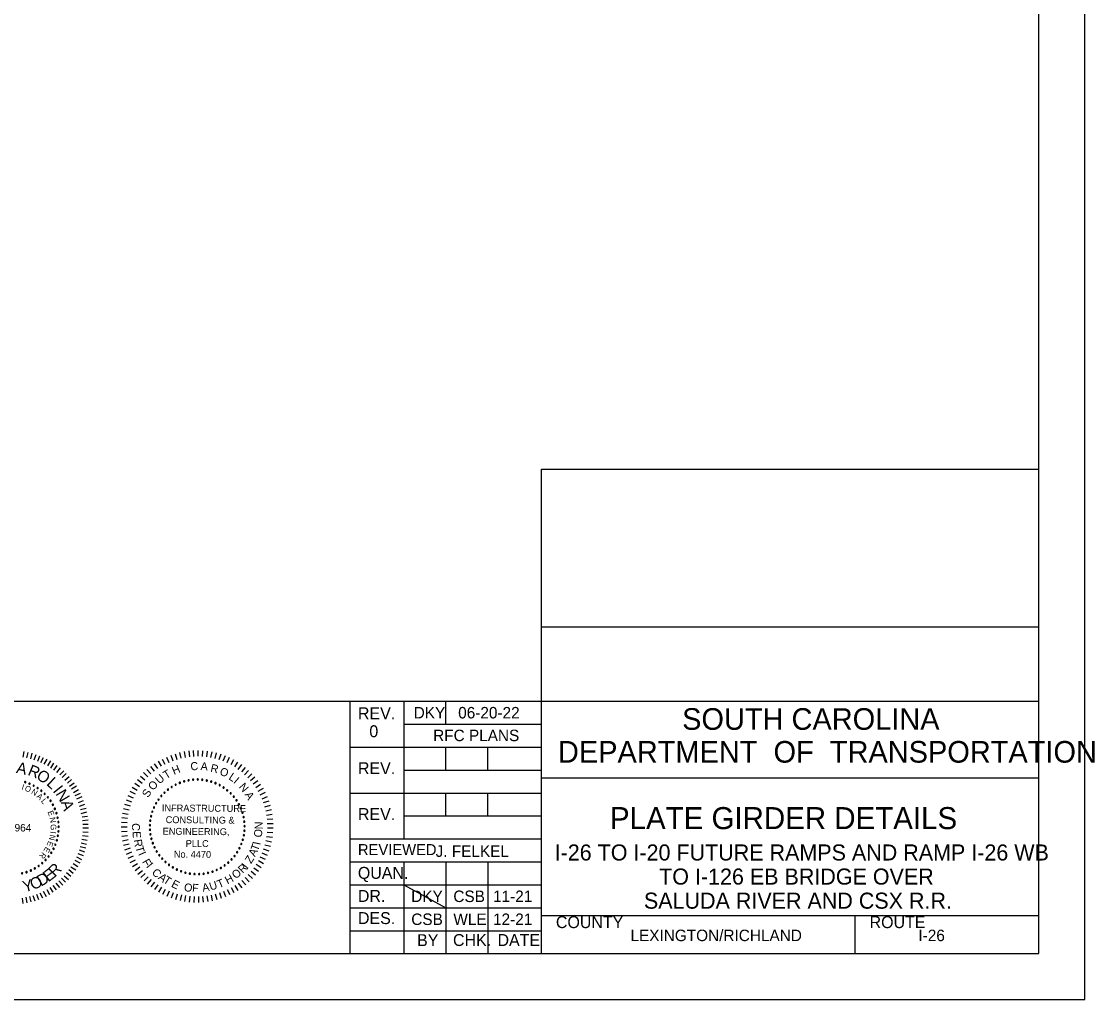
# Model space of a CAD drawing. Extents: x -305 to -161, y -187 to -99.
# Drawn here: x -207.5 to -160.75, y -187.49 to -144.87 of the extents above; entities that cross this region are included whole.
import ezdxf

# ---------------------------------------------------------------- set-up
doc = ezdxf.new("R2010")
doc.units = 0
for name, color, linetype in [('BR_BORDER LINES', 7, 'Continuous'), ('BR_TEXT', 7, 'Continuous'), ('Level 31', 7, 'Continuous')]:
    doc.layers.add(name, color=color, linetype=linetype)

msp = doc.modelspace()

# ---------------------------------------------------------------- linework, layer by layer
at = {"layer": 'BR_BORDER LINES'}
for p, q in [((-163.178, -185.489), (-163.178, -101.489)), ((-184.846, -185.489), (-184.846, -164.383)), ((-184.846, -164.383), (-163.178, -164.383)), ((-184.845, -171.242), (-163.178, -171.242)), ((-214.64, -174.489), (-193.18, -174.489)), ((-193.18, -185.489), (-193.18, -174.489)), ((-193.18, -174.489), (-163.178, -174.489)), ((-190.846, -174.489), (-190.846, -180.489)), ((-189.013, -175.489), (-189.013, -174.489)), ((-190.846, -175.489), (-184.846, -175.489)), ((-193.18, -176.489), (-184.846, -176.489)), ((-189.013, -177.489), (-189.013, -176.489)), ((-187.179, -177.489), (-187.179, -176.489)), ((-190.846, -177.489), (-184.846, -177.489)), ((-184.846, -177.822), (-184.846, -177.822)), ((-184.846, -177.823), (-163.178, -177.823)), ((-193.18, -178.489), (-184.846, -178.489)), ((-189.013, -179.489), (-189.013, -178.489)), ((-187.179, -179.489), (-187.179, -178.489)), ((-190.846, -179.489), (-184.846, -179.489)), ((-193.18, -180.489), (-184.846, -180.489)), ((-193.18, -181.489), (-184.846, -181.489)), ((-190.846, -181.489), (-190.846, -185.489)), ((-189.013, -181.489), (-189.013, -185.489)), ((-187.179, -181.489), (-187.179, -185.489)), ((-193.18, -182.489), (-184.846, -182.489)), ((-193.18, -183.489), (-184.846, -183.489)), ((-184.846, -183.823), (-163.178, -183.823)), ((-184.456, -183.823), (-163.178, -183.823)), ((-171.179, -185.489), (-171.179, -183.823)), ((-193.18, -184.489), (-184.846, -184.489)), ((-297.843, -185.489), (-163.178, -185.489))]:
    msp.add_line(p, q, dxfattribs=at)
at = {"layer": 'BR_TEXT'}
for p, q in [((-207.426, -176.925), (-207.382, -176.681)), ((-207.264, -176.957), (-207.208, -176.721)), ((-200.417, -176.685), (-200.373, -176.936)), ((-200.217, -176.656), (-200.188, -176.909)), ((-200.016, -176.64), (-200.002, -176.894)), ((-199.814, -176.636), (-199.816, -176.89)), ((-199.612, -176.644), (-199.63, -176.898)), ((-199.411, -176.664), (-199.444, -176.917)), ((-199.212, -176.697), (-199.26, -176.947)), ((-207.1, -176.999), (-207.036, -176.756)), ((-206.953, -177.042), (-206.865, -176.813)), ((-206.795, -177.095), (-206.708, -176.862)), ((-206.652, -177.165), (-206.54, -176.942)), ((-206.508, -177.234), (-206.383, -177.012)), ((-206.358, -177.308), (-206.229, -177.093)), ((-206.225, -177.405), (-206.089, -177.19)), ((-201.546, -177.106), (-201.415, -177.324)), ((-201.37, -177.007), (-201.252, -177.233)), ((-201.188, -176.92), (-201.084, -177.153)), ((-201.001, -176.844), (-200.912, -177.082)), ((-200.81, -176.779), (-200.735, -177.023)), ((-200.615, -176.726), (-200.555, -176.974)), ((-199.015, -176.741), (-199.079, -176.988)), ((-198.821, -176.798), (-198.9, -177.04)), ((-198.631, -176.866), (-198.724, -177.103)), ((-198.446, -176.946), (-198.553, -177.177)), ((-198.265, -177.037), (-198.387, -177.261)), ((-198.091, -177.139), (-198.226, -177.355)), ((-206.091, -177.492), (-205.946, -177.291)), ((-205.962, -177.596), (-205.799, -177.398)), ((-205.836, -177.696), (-205.663, -177.519)), ((-205.723, -177.807), (-205.55, -177.634)), ((-202.182, -177.601), (-202.002, -177.781)), ((-202.035, -177.463), (-201.866, -177.654)), ((-201.879, -177.334), (-201.723, -177.535)), ((-201.716, -177.215), (-201.572, -177.425)), ((-197.923, -177.251), (-198.071, -177.458)), ((-197.762, -177.373), (-197.922, -177.571)), ((-197.609, -177.505), (-197.781, -177.693)), ((-197.464, -177.646), (-197.647, -177.823)), ((-205.611, -177.932), (-205.421, -177.765)), ((-205.502, -178.06), (-205.316, -177.907)), ((-205.407, -178.194), (-205.21, -178.038)), ((-202.57, -178.065), (-202.36, -178.21)), ((-202.45, -177.903), (-202.25, -178.06)), ((-202.321, -177.748), (-202.13, -177.917)), ((-197.329, -177.795), (-197.522, -177.961)), ((-197.202, -177.952), (-197.405, -178.106)), ((-197.086, -178.117), (-197.298, -178.258)), ((-205.319, -178.312), (-205.109, -178.183)), ((-205.231, -178.46), (-205.017, -178.335)), ((-205.16, -178.598), (-204.929, -178.49)), ((-202.867, -178.593), (-202.634, -178.696)), ((-202.779, -178.411), (-202.553, -178.529)), ((-202.679, -178.235), (-202.461, -178.366)), ((-196.979, -178.289), (-197.199, -178.417)), ((-196.883, -178.467), (-197.111, -178.581)), ((-205.089, -178.746), (-204.862, -178.648)), ((-205.022, -178.901), (-204.795, -178.817)), ((-204.968, -179.063), (-204.738, -178.976)), ((-203.009, -178.97), (-202.766, -179.045)), ((-202.944, -178.779), (-202.705, -178.869)), ((-196.799, -178.65), (-197.033, -178.75)), ((-196.725, -178.838), (-196.965, -178.924)), ((-196.664, -179.03), (-196.908, -179.101)), ((-204.928, -179.207), (-204.688, -179.151)), ((-204.895, -179.376), (-204.654, -179.316)), ((-204.862, -179.52), (-204.625, -179.491)), ((-203.104, -179.363), (-202.853, -179.407)), ((-203.063, -179.165), (-202.815, -179.225)), ((-196.614, -179.226), (-196.862, -179.282)), ((-196.576, -179.424), (-196.827, -179.465)), ((-204.836, -179.685), (-204.592, -179.66)), ((-204.831, -179.843), (-204.59, -179.845)), ((-203.156, -179.965), (-202.901, -179.964)), ((-203.151, -179.764), (-202.897, -179.777)), ((-203.134, -179.562), (-202.881, -179.592)), ((-196.55, -179.625), (-196.804, -179.65)), ((-196.537, -179.826), (-196.791, -179.836)), ((-204.841, -180.334), (-204.598, -180.367)), ((-204.833, -180.18), (-204.593, -180.189)), ((-204.822, -180.008), (-204.578, -180.01)), ((-203.149, -180.167), (-202.895, -180.15)), ((-203.129, -180.368), (-202.877, -180.335)), ((-196.57, -180.43), (-196.822, -180.393)), ((-196.547, -180.23), (-196.8, -180.208)), ((-196.535, -180.028), (-196.79, -180.022)), ((-204.942, -180.824), (-204.702, -180.885)), ((-204.906, -180.656), (-204.666, -180.713)), ((-204.87, -180.499), (-204.634, -180.538)), ((-203.097, -180.568), (-202.847, -180.52)), ((-203.053, -180.765), (-202.807, -180.701)), ((-202.997, -180.959), (-202.755, -180.881)), ((-196.653, -180.825), (-196.899, -180.758)), ((-196.606, -180.629), (-196.855, -180.577)), ((-205.11, -181.272), (-204.884, -181.384)), ((-205.04, -181.125), (-204.814, -181.213)), ((-204.984, -180.971), (-204.755, -181.059)), ((-202.93, -181.149), (-202.693, -181.056)), ((-202.851, -181.335), (-202.62, -181.228)), ((-202.761, -181.516), (-202.536, -181.395)), ((-196.867, -181.392), (-197.096, -181.281)), ((-196.784, -181.207), (-197.02, -181.111)), ((-196.713, -181.018), (-196.954, -180.936)), ((-205.437, -181.826), (-205.243, -181.975)), ((-205.347, -181.71), (-205.139, -181.839)), ((-205.257, -181.563), (-205.045, -181.692)), ((-205.183, -181.416), (-204.954, -181.538)), ((-202.66, -181.69), (-202.443, -181.556)), ((-202.548, -181.859), (-202.34, -181.711)), ((-202.426, -182.02), (-202.228, -181.86)), ((-197.179, -181.91), (-197.385, -181.759)), ((-197.065, -181.743), (-197.279, -181.605)), ((-196.96, -181.57), (-197.182, -181.446)), ((-205.874, -182.313), (-205.704, -182.5)), ((-205.76, -182.194), (-205.589, -182.377)), ((-205.645, -182.092), (-205.458, -182.258)), ((-205.535, -181.959), (-205.351, -182.118)), ((-202.295, -182.173), (-202.107, -182.002)), ((-202.155, -182.319), (-201.977, -182.136)), ((-202.006, -182.455), (-201.84, -182.262)), ((-197.733, -182.495), (-197.895, -182.3)), ((-197.581, -182.362), (-197.756, -182.176)), ((-197.438, -182.219), (-197.623, -182.045)), ((-197.304, -182.068), (-197.5, -181.905)), ((-206.554, -182.768), (-206.432, -182.992)), ((-206.402, -182.69), (-206.277, -182.907)), ((-206.268, -182.602), (-206.135, -182.812)), ((-206.133, -182.517), (-205.99, -182.71)), ((-206.002, -182.415), (-205.842, -182.605)), ((-201.849, -182.582), (-201.695, -182.379)), ((-201.685, -182.699), (-201.543, -182.487)), ((-201.513, -182.806), (-201.385, -182.586)), ((-201.336, -182.903), (-201.221, -182.675)), ((-201.153, -182.988), (-201.053, -182.754)), ((-198.596, -183.012), (-198.692, -182.777)), ((-198.411, -182.93), (-198.522, -182.701)), ((-198.232, -182.837), (-198.356, -182.615)), ((-198.059, -182.734), (-198.196, -182.519)), ((-197.892, -182.62), (-198.042, -182.414)), ((-207.476, -183.065), (-207.437, -183.299)), ((-207.315, -183.022), (-207.262, -183.27)), ((-207.15, -182.996), (-207.09, -183.233)), ((-207.002, -182.949), (-206.918, -183.183)), ((-206.843, -182.902), (-206.759, -183.13)), ((-206.699, -182.835), (-206.591, -183.059)), ((-200.965, -183.062), (-200.879, -182.822)), ((-200.773, -183.125), (-200.702, -182.88)), ((-200.577, -183.175), (-200.521, -182.927)), ((-200.379, -183.214), (-200.338, -182.962)), ((-200.179, -183.24), (-200.154, -182.987)), ((-199.978, -183.254), (-199.968, -183)), ((-199.776, -183.256), (-199.781, -183.002)), ((-199.574, -183.246), (-199.595, -182.992)), ((-199.373, -183.223), (-199.41, -182.971)), ((-199.174, -183.188), (-199.226, -182.939)), ((-198.978, -183.142), (-199.045, -182.896)), ((-198.785, -183.083), (-198.867, -182.842))]:
    msp.add_line(p, q, dxfattribs=at)
for centre, start, end in [((-207.337, -178.015), 162.9114, 342.9114), ((-207.337, -178.015), 342.9114, 162.9114), ((-207.15, -178.083), 157.373, 337.373), ((-207.15, -178.083), 337.373, 157.373), ((-200.785, -178.127), 27.2191, 207.2191), ((-200.785, -178.127), 207.2191, 27.2191), ((-200.603, -178.045), 21.6807, 201.6807), ((-200.603, -178.045), 201.6807, 21.6807), ((-200.414, -177.98), 16.1422, 196.1422), ((-200.414, -177.98), 196.1422, 16.1422), ((-200.22, -177.935), 10.6038, 190.6038), ((-200.22, -177.935), 190.6038, 10.6038), ((-200.023, -177.908), 5.0653, 185.0653), ((-200.023, -177.908), 185.0653, 5.0653), ((-199.824, -177.9), 359.5268, 179.5268), ((-199.824, -177.9), 179.5268, 359.5268), ((-199.625, -177.912), 353.9884, 173.9884), ((-199.625, -177.912), 173.9884, 353.9884), ((-199.428, -177.943), 168.4499, 348.4499), ((-199.428, -177.943), 348.4499, 168.4499), ((-199.235, -177.992), 162.9114, 342.9114), ((-199.235, -177.992), 342.9114, 162.9114), ((-199.047, -178.06), 157.373, 337.373), ((-199.047, -178.06), 337.373, 157.373), ((-198.867, -178.146), 331.8345, 151.8345), ((-206.97, -178.169), 151.8345, 331.8345), ((-206.97, -178.169), 331.8345, 151.8345), ((-206.8, -178.272), 146.2961, 326.2961), ((-206.8, -178.272), 326.2961, 146.2961), ((-206.639, -178.39), 140.7576, 320.7576), ((-206.639, -178.39), 320.7576, 140.7576), ((-206.492, -178.524), 135.2191, 315.2191), ((-206.492, -178.524), 315.2191, 135.2191), ((-201.408, -178.617), 49.373, 229.373), ((-201.27, -178.472), 43.8345, 223.8345), ((-201.27, -178.472), 223.8345, 43.8345), ((-201.12, -178.341), 38.2961, 218.2961), ((-201.12, -178.341), 218.2961, 38.2961), ((-200.957, -178.226), 32.7576, 212.7576), ((-200.957, -178.226), 212.7576, 32.7576), ((-198.867, -178.146), 151.8345, 331.8345), ((-198.697, -178.249), 146.2961, 326.2961), ((-198.697, -178.249), 326.2961, 146.2961), ((-198.537, -178.368), 140.7576, 320.7576), ((-198.537, -178.368), 320.7576, 140.7576), ((-198.389, -178.502), 135.2191, 315.2191), ((-198.389, -178.502), 315.2191, 135.2191), ((-206.357, -178.671), 129.6807, 309.6807), ((-206.357, -178.671), 309.6807, 129.6807), ((-206.238, -178.831), 124.1422, 304.1422), ((-206.238, -178.831), 304.1422, 124.1422), ((-206.135, -179.001), 118.6038, 298.6038), ((-206.135, -179.001), 298.6038, 118.6038), ((-201.637, -178.942), 60.4499, 240.4499), ((-201.637, -178.942), 240.4499, 60.4499), ((-201.53, -178.774), 54.9114, 234.9114), ((-201.53, -178.774), 234.9114, 54.9114), ((-201.408, -178.617), 229.373, 49.373), ((-198.255, -178.649), 129.6807, 309.6807), ((-198.255, -178.649), 309.6807, 129.6807), ((-198.135, -178.809), 124.1422, 304.1422), ((-198.135, -178.809), 304.1422, 124.1422), ((-198.032, -178.979), 118.6038, 298.6038), ((-198.032, -178.979), 298.6038, 118.6038), ((-206.048, -179.181), 113.0653, 293.0653), ((-206.048, -179.181), 293.0653, 113.0653), ((-205.979, -179.368), 107.5268, 287.5268), ((-205.979, -179.368), 287.5268, 107.5268), ((-201.854, -179.497), 77.0653, 257.0653), ((-201.854, -179.497), 257.0653, 77.0653), ((-201.8, -179.305), 71.5268, 251.5268), ((-201.8, -179.305), 251.5268, 71.5268), ((-201.727, -179.12), 65.9884, 245.9884), ((-201.727, -179.12), 245.9884, 65.9884), ((-197.945, -179.159), 113.0653, 293.0653), ((-197.945, -179.159), 293.0653, 113.0653), ((-197.876, -179.346), 107.5268, 287.5268), ((-197.876, -179.346), 287.5268, 107.5268), ((-197.826, -179.538), 101.9884, 281.9884), ((-197.826, -179.538), 281.9884, 101.9884), ((-205.929, -179.561), 101.9884, 281.9884), ((-205.929, -179.561), 281.9884, 101.9884), ((-205.897, -179.758), 96.4499, 276.4499), ((-205.885, -179.957), 90.9114, 270.9114), ((-205.897, -179.758), 276.4499, 96.4499), ((-205.885, -179.957), 270.9114, 90.9114), ((-201.906, -179.892), 88.1422, 268.1422), ((-201.89, -179.693), 82.6038, 262.6038), ((-201.906, -179.892), 268.1422, 88.1422), ((-201.89, -179.693), 262.6038, 82.6038), ((-197.795, -179.735), 96.4499, 276.4499), ((-197.782, -179.934), 90.9114, 270.9114), ((-197.795, -179.735), 276.4499, 96.4499), ((-197.782, -179.934), 270.9114, 90.9114), ((-205.918, -180.353), 79.8345, 259.8345), ((-205.918, -180.353), 259.8345, 79.8345), ((-205.892, -180.156), 85.373, 265.373), ((-205.892, -180.156), 265.373, 85.373), ((-201.904, -180.091), 93.6807, 273.6807), ((-201.882, -180.289), 99.2191, 279.2191), ((-201.904, -180.091), 273.6807, 93.6807), ((-201.882, -180.289), 279.2191, 99.2191), ((-201.841, -180.484), 104.7576, 284.7576), ((-201.841, -180.484), 284.7576, 104.7576), ((-197.815, -180.331), 79.8345, 259.8345), ((-197.815, -180.331), 259.8345, 79.8345), ((-197.789, -180.133), 85.373, 265.373), ((-197.789, -180.133), 265.373, 85.373), ((-206.108, -180.918), 63.2191, 243.2191), ((-206.108, -180.918), 243.2191, 63.2191), ((-206.026, -180.737), 68.7576, 248.7576), ((-206.026, -180.737), 248.7576, 68.7576), ((-205.963, -180.548), 74.2961, 254.2961), ((-205.963, -180.548), 254.2961, 74.2961), ((-201.781, -180.675), 110.2961, 290.2961), ((-201.781, -180.675), 290.2961, 110.2961), ((-201.703, -180.858), 115.8345, 295.8345), ((-201.703, -180.858), 295.8345, 115.8345), ((-198.005, -180.896), 63.2191, 243.2191), ((-198.005, -180.896), 243.2191, 63.2191), ((-197.924, -180.714), 68.7576, 248.7576), ((-197.924, -180.714), 248.7576, 68.7576), ((-197.86, -180.525), 74.2961, 254.2961), ((-197.86, -180.525), 254.2961, 74.2961), ((-206.451, -181.406), 46.6038, 226.6038), ((-206.451, -181.406), 226.6038, 46.6038), ((-206.321, -181.255), 52.1422, 232.1422), ((-206.321, -181.255), 232.1422, 52.1422), ((-206.207, -181.092), 57.6807, 237.6807), ((-206.207, -181.092), 237.6807, 57.6807), ((-201.608, -181.033), 121.373, 301.373), ((-201.608, -181.033), 301.373, 121.373), ((-201.497, -181.199), 126.9114, 306.9114), ((-201.497, -181.199), 306.9114, 126.9114), ((-201.37, -181.352), 132.4499, 312.4499), ((-201.37, -181.352), 312.4499, 132.4499), ((-198.349, -181.383), 46.6038, 226.6038), ((-198.349, -181.383), 226.6038, 46.6038), ((-198.219, -181.232), 52.1422, 232.1422), ((-198.219, -181.232), 232.1422, 52.1422), ((-198.104, -181.069), 57.6807, 237.6807), ((-198.104, -181.069), 237.6807, 57.6807), ((-207.097, -181.865), 24.4499, 204.4499), ((-207.097, -181.865), 204.4499, 24.4499), ((-206.92, -181.774), 29.9884, 209.9884), ((-206.92, -181.774), 209.9884, 29.9884), ((-206.752, -181.667), 35.5268, 215.5268), ((-206.752, -181.667), 215.5268, 35.5268), ((-206.596, -181.543), 41.0653, 221.0653), ((-206.596, -181.543), 221.0653, 41.0653), ((-201.228, -181.493), 137.9884, 317.9884), ((-201.228, -181.493), 317.9884, 137.9884), ((-201.074, -181.619), 143.5268, 323.5268), ((-201.074, -181.619), 323.5268, 143.5268), ((-200.909, -181.73), 149.0653, 329.0653), ((-200.909, -181.73), 329.0653, 149.0653), ((-200.733, -181.825), 154.6038, 334.6038), ((-200.733, -181.825), 334.6038, 154.6038), ((-198.995, -181.842), 24.4499, 204.4499), ((-198.995, -181.842), 204.4499, 24.4499), ((-198.817, -181.752), 29.9884, 209.9884), ((-198.817, -181.752), 209.9884, 29.9884), ((-198.649, -181.644), 35.5268, 215.5268), ((-198.649, -181.644), 215.5268, 35.5268), ((-198.493, -181.521), 41.0653, 221.0653), ((-198.493, -181.521), 221.0653, 41.0653), ((-207.474, -181.993), 13.373, 193.373), ((-207.474, -181.993), 193.373, 13.373), ((-207.283, -181.938), 18.9114, 198.9114), ((-207.283, -181.938), 198.9114, 18.9114), ((-200.549, -181.902), 160.1422, 340.1422), ((-200.549, -181.902), 340.1422, 160.1422), ((-200.359, -181.961), 165.6807, 345.6807), ((-200.359, -181.961), 345.6807, 165.6807), ((-200.164, -182.001), 171.2191, 351.2191), ((-200.164, -182.001), 351.2191, 171.2191), ((-199.965, -182.022), 176.7576, 356.7576), ((-199.965, -182.022), 356.7576, 176.7576), ((-199.766, -182.024), 2.2961, 182.2961), ((-199.766, -182.024), 182.2961, 2.2961), ((-199.568, -182.007), 7.8345, 187.8345), ((-199.568, -182.007), 187.8345, 7.8345), ((-199.372, -181.971), 13.373, 193.373), ((-199.372, -181.971), 193.373, 13.373), ((-199.18, -181.916), 18.9114, 198.9114), ((-199.18, -181.916), 198.9114, 18.9114)]:
    msp.add_arc(centre, 0.028, start, end, dxfattribs=at)
at = {"layer": 'Level 31'}
for p, q in [((-174.011, -179.583), (-174.011, -179.583)), ((-190.846, -182.489), (-189.013, -183.489))]:
    msp.add_line(p, q, dxfattribs=at)
msp.add_lwpolyline([(-305.176, -187.489), (-161.176, -187.489), (-161.176, -99.489), (-305.176, -99.489)], close=True, dxfattribs=at)

# ---------------------------------------------------------------- texts
at = {"layer": 'BR_TEXT'}
for s, height, p in [('REV.', 0.52, (-192.841, -175.277)), ('DKY', 0.5, (-190.413, -175.239)), ('06-20-22', 0.5, (-188.475, -175.239)), ('SOUTH CAROLINA', 0.94348, (-178.718, -175.735)), ('0', 0.52, (-192.345, -176.057)), ('RFC PLANS', 0.5, (-189.566, -176.229)), ('DEPARTMENT  OF  TRANSPORTATION', 0.94348, (-184.129, -177.166)), ('REV.', 0.52, (-192.841, -177.667)), ('REV.', 0.52, (-192.841, -179.667)), ('PLATE GIRDER DETAILS', 0.96, (-181.861, -180.063)), ('REVIEWED', 0.48, (-192.843, -181.195)), ('J. FELKEL', 0.5, (-189.458, -181.272)), ('I-26 TO I-20 FUTURE RAMPS AND RAMP I-26 WB', 0.7, (-184.272, -181.43)), ('QUAN.', 0.52, (-192.846, -182.229)), ('TO I-126 EB BRIDGE OVER', 0.7, (-179.72, -182.48)), ('DR.', 0.52, (-192.845, -183.235)), ('DKY', 0.5, (-190.522, -183.24)), ('CSB', 0.5, (-188.686, -183.24)), ('11-21', 0.5, (-186.957, -183.24)), ('SALUDA RIVER AND CSX R.R.', 0.7, (-180.383, -183.53)), ('DES.', 0.52, (-192.841, -184.2)), ('CSB', 0.5, (-190.519, -184.24)), ('12-21', 0.5, (-186.957, -184.24)), ('WLE', 0.5, (-188.684, -184.24)), ('COUNTY', 0.52, (-184.217, -184.376)), ('ROUTE', 0.52, (-170.55, -184.376)), ('BY', 0.52, (-190.265, -185.161)), ('CHK.', 0.52, (-188.701, -185.156)), ('DATE', 0.52, (-186.761, -185.156)), ('LEXINGTON/RICHLAND', 0.49998, (-180.968, -184.944)), ('I-26', 0.5, (-168.424, -184.944))]:
    msp.add_text(s, height=height, dxfattribs=at).set_placement(p)
for s, height, rotation, p in [('A', 0.496, 348.1981, (-207.755, -177.609)), ('C', 0.349, 4.7281, (-200.126, -177.506)), ('A', 0.349, 355.6981, (-199.708, -177.486)), ('R', 0.496, 337.4344, (-207.262, -177.689)), ('O', 0.496, 326.5869, (-206.893, -177.836)), ('T', 0.349, 31.8182, (-201.196, -177.894)), ('H', 0.349, 22.7882, (-200.857, -177.704)), ('R', 0.349, 346.6681, (-199.291, -177.554)), ('O', 0.349, 337.638, (-198.9, -177.673)), ('L', 0.349, 327.108, (-198.504, -177.875)), ('I', 0.249, 343.1136, (-207.515, -178.335)), ('L', 0.496, 315.9488, (-206.442, -178.107)), ('O', 0.349, 49.8782, (-201.757, -178.403)), ('U', 0.349, 40.8482, (-201.49, -178.119)), ('I', 0.349, 319.578, (-198.294, -178.026)), ('N', 0.349, 310.548, (-198.051, -178.23)), ('O', 0.249, 338.4392, (-207.381, -178.376)), ('N', 0.249, 328.2042, (-207.103, -178.501)), ('A', 0.249, 318.657, (-206.867, -178.662)), ('I', 0.496, 308.6613, (-206.157, -178.404)), ('N', 0.496, 300.7037, (-206.035, -178.521)), ('S', 0.349, 58.9083, (-201.979, -178.715)), ('A', 0.349, 301.5179, (-197.791, -178.559)), ('L', 0.249, 309.4546, (-206.668, -178.851)), ('A', 0.496, 289.4792, (-205.798, -178.894)), ('INFRASTRUCTURE', 0.29909, 359.5268, (-201.385, -179.286)), ('E', 0.249, 291.049, (-206.372, -179.312)), ('CONSULTING &', 0.29909, 359.5268, (-201.22, -179.8)), ('No. 29964', 0.327, 359.5268, (-209.092, -180.153)), ('N', 0.249, 281.8466, (-206.283, -179.572)), ('G', 0.249, 272.2995, (-206.237, -179.853)), ('C', 0.349, 267.025, (-202.679, -179.795)), ('N', 0.349, 89.2085, (-196.993, -180.074)), ('N', 0.249, 257.7339, (-206.256, -180.287)), ('I', 0.249, 262.4084, (-206.238, -180.149)), ('E', 0.349, 273.025, (-202.662, -180.161)), ('ENGINEERING,', 0.29909, 359.5268, (-201.354, -180.302)), ('O', 0.349, 83.2085, (-197.038, -180.44)), ('E', 0.249, 238.9844, (-206.44, -180.814)), ('E', 0.249, 248.1867, (-206.328, -180.563)), ('R', 0.349, 279.025, (-202.61, -180.531)), ('T', 0.349, 285.025, (-202.541, -180.846)), ('PLLC', 0.2991, 359.5268, (-200.347, -180.836)), ('T', 0.349, 69.3954, (-197.203, -181.047)), ('I', 0.349, 77.9093, (-197.1, -180.777)), ('R', 0.249, 229.782, (-206.591, -181.044)), ('I', 0.349, 293.7713, (-202.422, -181.138)), ('F', 0.349, 299.7713, (-202.257, -181.482)), ('No. 4470', 0.2991, 359.5268, (-200.865, -181.304)), ('Z', 0.349, 57.3954, (-197.501, -181.594)), ('A', 0.349, 63.3954, (-197.326, -181.288)), ('E', 0.494, 37.5339, (-206.33, -182.388)), ('R', 0.494, 44.5947, (-206.048, -182.172)), ('I', 0.349, 308.5268, (-202.089, -181.698)), ('C', 0.349, 314.5268, (-201.851, -181.978)), ('O', 0.349, 38.5268, (-198.169, -182.254)), ('R', 0.349, 44.5268, (-197.863, -182.014)), ('I', 0.349, 52.3339, (-197.665, -181.825)), ('Y', 0.494, 14.8649, (-207.378, -182.822)), ('O', 0.494, 22.4212, (-207.011, -182.724)), ('D', 0.494, 30.1015, (-206.654, -182.575)), ('A', 0.349, 320.5268, (-201.575, -182.213)), ('T', 0.349, 326.5268, (-201.357, -182.366)), ('E', 0.349, 332.5268, (-201.003, -182.558)), ('U', 0.349, 16.5268, (-199.261, -182.742)), ('T', 0.349, 22.5268, (-198.894, -182.645)), ('H', 0.349, 28.5268, (-198.522, -182.478)), ('O', 0.349, 350.5268, (-200.442, -182.753)), ('F', 0.349, 356.5268, (-200.076, -182.79)), ('A', 0.349, 10.5268, (-199.597, -182.796))]:
    msp.add_text(s, height=height, rotation=rotation, dxfattribs=at).set_placement(p)

doc.saveas('drawing.dxf')
